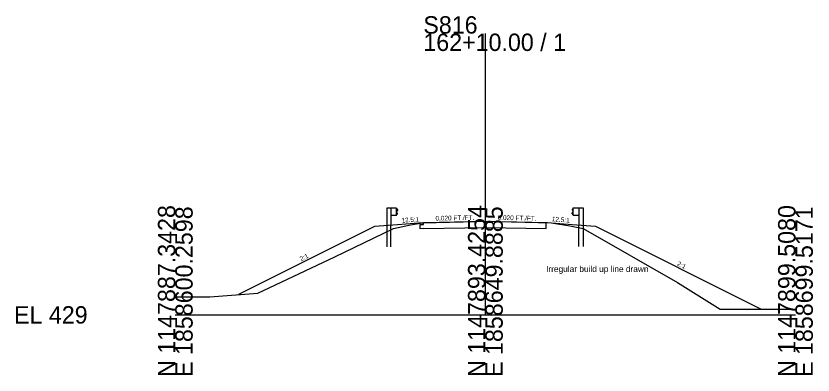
# Model space of a CAD drawing. Extents: x -76 to 4323, y -10 to 2055.
# Drawn here: x 4194.3 to 4322.8, y 490.3 to 548.2 of the extents above; entities that cross this region are included whole.
import ezdxf

# ---------------------------------------------------------------- set-up
doc = ezdxf.new("R2010")
doc.units = 0
for name, color, linetype in [('Default', 7, 'Continuous'), ('RD_GPK_XS_Cell', 7, 'Continuous'), ('RD_XS_Base', 7, 'Continuous'), ('RD_XS_EarthShd', 7, 'Continuous'), ('RD_XS_ExGround', 7, 'Continuous'), ('RD_XS_GR', 7, 'Continuous'), ('RD_XS_Pave', 7, 'Continuous'), ('RD_XS_TieSlope', 7, 'Continuous'), ('RD_XS_TX_ShdSlope', 7, 'Continuous'), ('RD_XS_TX_Slope', 7, 'Continuous'), ('RD_XS_TX_Warning', 7, 'Continuous')]:
    doc.layers.add(name, color=color, linetype=linetype)

msp = doc.modelspace()

# ---------------------------------------------------------------- linework, layer by layer
at = {"layer": 'Default'}
for p, q in [((4260, 514.9), (4270, 515.1)), ((4270, 515.1), (4280, 514.9))]:
    msp.add_line(p, q, dxfattribs=at)
at = {"layer": 'RD_GPK_XS_Cell'}
for p, q in [((4270, 500), (4270, 545.32)), ((4220, 500), (4270, 500)), ((4270, 500), (4320, 500))]:
    msp.add_line(p, q, dxfattribs=at)
at = {"layer": 'RD_XS_Base'}
for p, q in [((4279.8, 513.9), (4279.8, 514.9)), ((4260, 513.9), (4270, 514.1)), ((4270, 514.1), (4279.8, 513.9))]:
    msp.add_line(p, q, dxfattribs=at)
at = {"layer": 'RD_XS_EarthShd'}
for p, q in [((4255.85, 514.53), (4252.1, 514.23)), ((4255.85, 514.53), (4252.1, 514.23)), ((4259.85, 514.85), (4255.85, 514.53)), ((4259.85, 514.85), (4255.85, 514.53)), ((4280, 514.9), (4284, 514.58)), ((4280, 514.9), (4284, 514.58)), ((4284, 514.58), (4287.75, 514.28)), ((4284, 514.58), (4287.75, 514.28))]:
    msp.add_line(p, q, dxfattribs=at)
at = {"layer": 'RD_XS_ExGround'}
msp.add_lwpolyline([(4220, 502.89), (4225.57, 502.92), (4233.3, 503.5), (4245.74, 509.35), (4255.19, 513.94), (4257.93, 514.51), (4259.85, 514.85), (4266.4, 515), (4270.28, 515.11), (4274.19, 515.01), (4280.65, 514.83), (4283.6, 514.34), (4285.77, 513.93), (4300.96, 505.21), (4307.87, 500.93), (4318.62, 500.92), (4320, 500.91)], dxfattribs=at)
at = {"layer": 'RD_XS_GR'}
for p, q in [((4254.1, 517.19), (4254.1, 514.39)), ((4254.77, 517.19), (4254.1, 517.19)), ((4254.1, 517.19), (4254.1, 514.39)), ((4254.77, 517.19), (4254.1, 517.19)), ((4254.77, 517.19), (4254.77, 514.45)), ((4255.68, 517.19), (4254.77, 517.19)), ((4254.77, 517.19), (4254.77, 514.45)), ((4255.68, 517.19), (4254.77, 517.19)), ((4255.68, 516.02), (4255.68, 517.19)), ((4255.68, 516.02), (4255.68, 517.19)), ((4255.68, 517.12), (4255.85, 516.92)), ((4255.68, 517.12), (4255.85, 516.92)), ((4255.85, 516.87), (4255.68, 516.67)), ((4255.85, 516.87), (4255.68, 516.67)), ((4255.85, 516.92), (4255.85, 516.87)), ((4255.85, 516.92), (4255.85, 516.87)), ((4284.17, 517.16), (4284, 516.96)), ((4284.17, 517.16), (4284, 516.96)), ((4284, 516.96), (4284, 516.91)), ((4284, 516.96), (4284, 516.91)), ((4284, 516.91), (4284.17, 516.71)), ((4284, 516.91), (4284.17, 516.71)), ((4284.17, 516.07), (4284.17, 517.24)), ((4284.17, 517.24), (4285.08, 517.24)), ((4284.17, 516.07), (4284.17, 517.24)), ((4284.17, 517.24), (4285.08, 517.24)), ((4285.08, 517.24), (4285.08, 514.49)), ((4285.08, 517.24), (4285.75, 517.24)), ((4285.08, 517.24), (4285.08, 514.49)), ((4285.08, 517.24), (4285.75, 517.24)), ((4285.75, 517.24), (4285.75, 514.44)), ((4285.75, 517.24), (4285.75, 514.44)), ((4255.68, 516.02), (4254.77, 516.02)), ((4255.68, 516.02), (4254.77, 516.02)), ((4255.85, 516.35), (4255.68, 516.55)), ((4255.85, 516.35), (4255.68, 516.55)), ((4255.68, 516.1), (4255.85, 516.3)), ((4255.68, 516.1), (4255.85, 516.3)), ((4255.85, 516.3), (4255.85, 516.35)), ((4255.85, 516.3), (4255.85, 516.35)), ((4284, 516.39), (4284.17, 516.59)), ((4284, 516.39), (4284.17, 516.59)), ((4284, 516.34), (4284, 516.39)), ((4284, 516.34), (4284, 516.39)), ((4284.17, 516.14), (4284, 516.34)), ((4284.17, 516.14), (4284, 516.34)), ((4284.17, 516.07), (4285.08, 516.07)), ((4284.17, 516.07), (4285.08, 516.07)), ((4254.1, 514.39), (4254.1, 510.98)), ((4254.77, 510.98), (4254.77, 514.45)), ((4254.77, 510.98), (4254.77, 514.45)), ((4285.08, 511.02), (4285.08, 514.49)), ((4285.08, 511.02), (4285.08, 514.49)), ((4285.75, 514.44), (4285.75, 511.02)), ((4285.75, 514.44), (4285.75, 511.02))]:
    msp.add_line(p, q, dxfattribs=at)
at = {"layer": 'RD_XS_Pave'}
for p, q in [((4259.5, 514.56), (4260, 514.57)), ((4259.5, 513.89), (4259.5, 514.56)), ((4260, 514.57), (4260, 514.9)), ((4260, 513.9), (4259.5, 513.89))]:
    msp.add_line(p, q, dxfattribs=at)
at = {"layer": 'RD_XS_TieSlope'}
for p, q in [((4252.1, 514.23), (4230.17, 503.27)), ((4287.75, 514.28), (4314.46, 500.93))]:
    msp.add_line(p, q, dxfattribs=at)

# ---------------------------------------------------------------- texts
at = {"layer": 'RD_GPK_XS_Cell'}
for s, p in [('S816', (4260, 545.32)), ('162+10.00 / 1', (4260, 542.52)), ('EL 429', (4194, 498.6))]:
    msp.add_text(s, height=2.8, dxfattribs=at).set_placement(p)
for s, p in [('N 1147887.3428', (4220, 490)), ('E 1858600.2598', (4222.8, 490)), ('N 1147893.4254', (4270, 490)), ('E 1858649.8885', (4272.8, 490)), ('N 1147899.5080', (4320, 490)), ('E 1858699.5171', (4322.8, 490))]:
    msp.add_text(s, height=2.8, rotation=90, dxfattribs=at).set_placement(p)
at = {"layer": 'RD_XS_TX_ShdSlope'}
for rotation, p in [(4.5739, (4256.51, 514.84)), (4.5739, (4256.51, 514.84)), (355.4261, (4280.7, 515.09))]:
    msp.add_text('12.5:1', height=0.75, rotation=rotation, dxfattribs=at).set_placement(p)
at = {"layer": 'RD_XS_TX_Slope'}
for s, rotation, p in [('0.020 FT./FT.', 1.1458, (4261.97, 515.19)), ('0.020 FT./FT.', 358.8542, (4271.98, 515.31)), ('2:1', 26.5651, (4240.29, 508.61)), ('2:1', 333.4349, (4300.84, 508.01))]:
    msp.add_text(s, height=0.75, rotation=rotation, dxfattribs=at).set_placement(p)
at = {"layer": 'RD_XS_TX_Warning'}
msp.add_text('Irregular build up line drawn', height=1, dxfattribs=at).set_placement((4279.8, 506.9))

doc.saveas('drawing.dxf')
